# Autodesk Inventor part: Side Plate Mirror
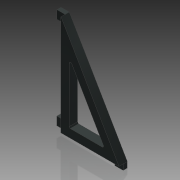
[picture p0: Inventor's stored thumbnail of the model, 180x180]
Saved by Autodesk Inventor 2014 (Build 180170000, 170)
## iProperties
Created: 2015-07
Part Number: Side Plate Mirror
Material: Generic
Document SubType Name: Modeling
Designer: Brad Factor
Density: 1 g/cm^3
Appearance: Default
Author: Brad Factor
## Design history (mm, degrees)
derived "Side Plate.ipt"
feature "Solid1::Side Plate.ipt" dims "d0" = 10
tag "TaggingFeature1"
body "Solid1"
